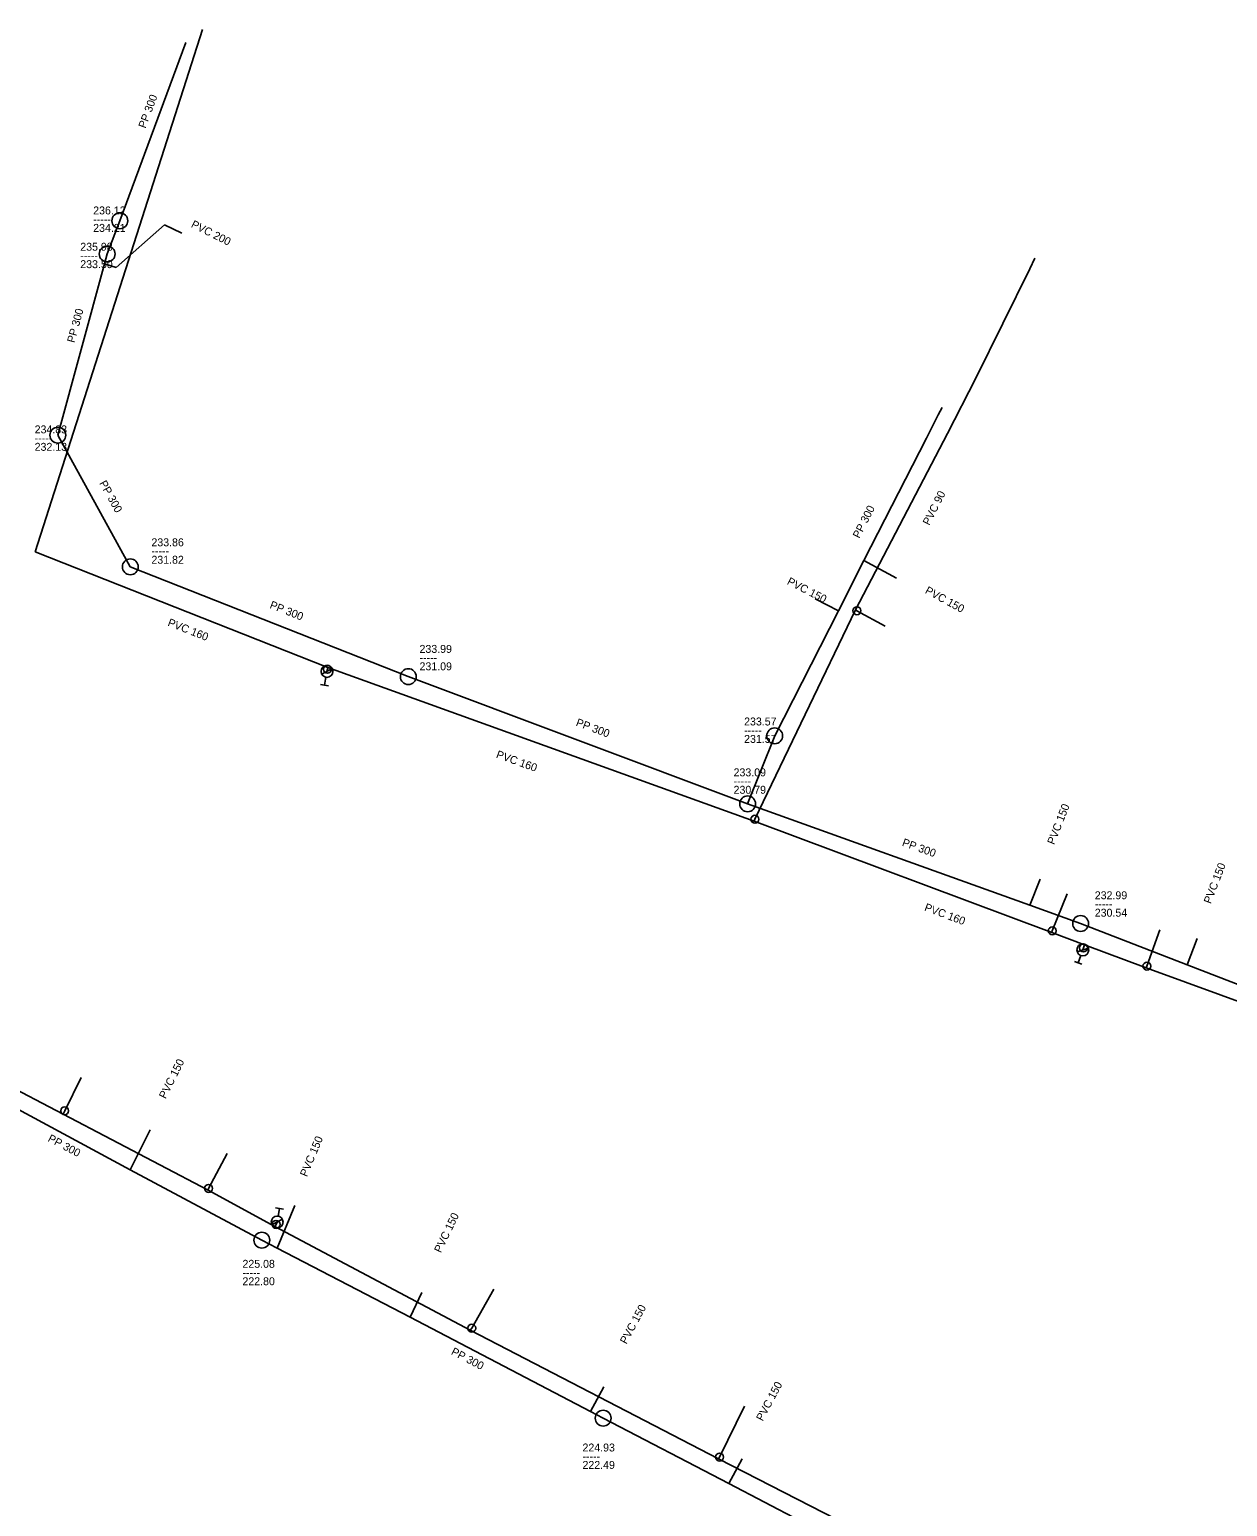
# Model space of a CAD drawing. Extents: x -771542 to -770341, y -1050442 to -1049881.
# Drawn here: x -771242.8 to -771091.6, y -1050160.7 to -1049974.4 of the extents above; entities that cross this region are included whole.
import ezdxf

# ---------------------------------------------------------------- set-up
doc = ezdxf.new("R2010")
doc.units = 0
doc.layers.add('Level 0', color=7, linetype='Continuous')

msp = doc.modelspace()

# ---------------------------------------------------------------- linework, layer by layer
at = {"layer": 'Level 0'}
for p, q in [((-771220.95, -1049974.35), (-771242.06, -1050040.24)), ((-771223.04, -1049976), (-771231.38, -1049998.48)), ((-771231.38, -1049998.48), (-771232.99, -1050002.67)), ((-771231.83, -1050004.36), (-771225.73, -1049999)), ((-771225.73, -1049999), (-771223.55, -1050000.04)), ((-771232.99, -1050002.67), (-771233.33, -1050003.92)), ((-771116.54, -1050004.53), (-771115.9, -1050003.22)), ((-771233.33, -1050003.92), (-771239.22, -1050025.54)), ((-771233.33, -1050003.92), (-771231.83, -1050004.36)), ((-771123.35, -1050018.33), (-771116.54, -1050004.53)), ((-771126.9, -1050025.32), (-771123.35, -1050018.33)), ((-771127.61, -1050022.04), (-771128.08, -1050022.96)), ((-771128.08, -1050022.96), (-771129.59, -1050025.93)), ((-771239.22, -1050025.54), (-771230.07, -1050042.15)), ((-771138.55, -1050047.57), (-771126.9, -1050025.32)), ((-771129.59, -1050025.93), (-771137.46, -1050041.37)), ((-771242.06, -1050040.24), (-771205.12, -1050054.85)), ((-771230.07, -1050042.15), (-771194.98, -1050056.01)), ((-771137.46, -1050041.37), (-771140.68, -1050047.69)), ((-771137.46, -1050041.37), (-771133.36, -1050043.59)), ((-771140.68, -1050047.69), (-771143.62, -1050046.18)), ((-771151.23, -1050074.01), (-771138.55, -1050047.57)), ((-771140.68, -1050047.69), (-771148.73, -1050063.48)), ((-771138.55, -1050047.57), (-771138.35, -1050047.7)), ((-771138.35, -1050047.7), (-771134.78, -1050049.66)), ((-771204.58, -1050055), (-771205.9, -1050055.7)), ((-771205.19, -1050055.08), (-771205.24, -1050055.35)), ((-771205.12, -1050054.85), (-771205.19, -1050055.08)), ((-771205.12, -1050054.85), (-771151.31, -1050074.25)), ((-771205.05, -1050057.16), (-771206.04, -1050056.99)), ((-771205.37, -1050056.09), (-771205.54, -1050057.07)), ((-771194.98, -1050056.01), (-771152.15, -1050072.06)), ((-771148.73, -1050063.48), (-771152.15, -1050072.06)), ((-771152.15, -1050072.06), (-771116.52, -1050084.87)), ((-771151.31, -1050074.25), (-771151.23, -1050074.01)), ((-771151.31, -1050074.25), (-771113.77, -1050088.3)), ((-771116.52, -1050084.87), (-771115.22, -1050081.57)), ((-771113.69, -1050088.09), (-771111.81, -1050083.42)), ((-771116.52, -1050084.87), (-771110.12, -1050087.17)), ((-771110.12, -1050087.17), (-771096.66, -1050092.37)), ((-771113.77, -1050088.3), (-771113.69, -1050088.09)), ((-771113.77, -1050088.3), (-771109.61, -1050089.86)), ((-771101.75, -1050092.55), (-771100.13, -1050087.96)), ((-771096.66, -1050092.37), (-771095.39, -1050089.06)), ((-771109.13, -1050090.26), (-771110.55, -1050090.72)), ((-771110.1, -1050091.19), (-771110.44, -1050092.13)), ((-771109.76, -1050090.25), (-771109.84, -1050090.49)), ((-771109.61, -1050089.86), (-771109.76, -1050090.25)), ((-771109.61, -1050089.86), (-771101.83, -1050092.77)), ((-771109.97, -1050092.31), (-771110.91, -1050091.96)), ((-771101.83, -1050092.77), (-771101.75, -1050092.55)), ((-771101.83, -1050092.77), (-771069.68, -1050104.49)), ((-771096.66, -1050092.37), (-771069.74, -1050102.77)), ((-771252.68, -1050106.1), (-771230.08, -1050118.23)), ((-771238.56, -1050111.22), (-771246.42, -1050107.1)), ((-771238.35, -1050110.8), (-771236.28, -1050106.58)), ((-771238.56, -1050111.22), (-771238.35, -1050110.8)), ((-771220.23, -1050120.83), (-771238.56, -1050111.22)), ((-771230.08, -1050118.23), (-771227.56, -1050113.21)), ((-771220.19, -1050120.59), (-771217.86, -1050116.2)), ((-771230.08, -1050118.23), (-771213.46, -1050127.13)), ((-771220.23, -1050120.83), (-771220.19, -1050120.59)), ((-771211.82, -1050125.38), (-771220.23, -1050120.83)), ((-771211.72, -1050123.03), (-771210.73, -1050123.2)), ((-771211.54, -1050128.13), (-771209.3, -1050122.77)), ((-771212.19, -1050125.19), (-771210.87, -1050124.49)), ((-771211.66, -1050125.14), (-771211.53, -1050124.84)), ((-771211.4, -1050124.1), (-771211.23, -1050123.12)), ((-771211.82, -1050125.38), (-771211.66, -1050125.14)), ((-771211.82, -1050125.38), (-771187.15, -1050138.47)), ((-771213.46, -1050127.13), (-771211.54, -1050128.13)), ((-771211.54, -1050128.13), (-771194.76, -1050136.86)), ((-771194.76, -1050136.86), (-771193.26, -1050133.75)), ((-771186.97, -1050138.23), (-771184.19, -1050133.31)), ((-771194.76, -1050136.86), (-771171.97, -1050148.76)), ((-771187.15, -1050138.47), (-771186.97, -1050138.23)), ((-771187.15, -1050138.47), (-771155.81, -1050154.74)), ((-771171.97, -1050148.76), (-771170.29, -1050145.63)), ((-771171.97, -1050148.76), (-771170.38, -1050149.59)), ((-771155.69, -1050154.5), (-771152.54, -1050148.08)), ((-771170.38, -1050149.59), (-771154.52, -1050157.84)), ((-771155.81, -1050154.74), (-771155.69, -1050154.5)), ((-771154.52, -1050157.84), (-771152.84, -1050154.7)), ((-771155.81, -1050154.74), (-771094.72, -1050185.98)), ((-771154.52, -1050157.84), (-771125.58, -1050172.94))]:
    msp.add_line(p, q, dxfattribs=at)
for centre, radius in [((-771231.38, -1049998.48), 1), ((-771232.99, -1050002.67), 1), ((-771239.22, -1050025.54), 1), ((-771230.07, -1050042.15), 1), ((-771138.35, -1050047.7), 0.5), ((-771205.24, -1050055.35), 0.75), ((-771205.19, -1050055.08), 0.5), ((-771194.98, -1050056.01), 1), ((-771148.73, -1050063.48), 1), ((-771152.15, -1050072.06), 1), ((-771151.23, -1050074.01), 0.5), ((-771113.69, -1050088.09), 0.5), ((-771110.12, -1050087.17), 1), ((-771109.84, -1050090.49), 0.75), ((-771109.76, -1050090.25), 0.5), ((-771101.75, -1050092.55), 0.5), ((-771238.35, -1050110.8), 0.5), ((-771220.19, -1050120.59), 0.5), ((-771211.53, -1050124.84), 0.75), ((-771211.66, -1050125.14), 0.5), ((-771213.46, -1050127.13), 1), ((-771186.97, -1050138.23), 0.5), ((-771170.38, -1050149.59), 1), ((-771155.69, -1050154.5), 0.5)]:
    msp.add_circle(centre, radius, dxfattribs=at)

# ---------------------------------------------------------------- texts
for s, rotation, p in [('PP 300', 69.645, (-771228.15, -1049986.89)), ('PVC 200', 333.325, (-771222.48, -1049999.25)), ('PP 300', 74.784, (-771237.11, -1050013.95)), ('PP 300', 298.849, (-771234.01, -1050031.59)), ('PVC 90', 63.075, (-771129.22, -1050037)), ('PP 300', 62.991, (-771138.05, -1050038.64)), ('PVC 150', 332.815, (-771147.26, -1050044.31)), ('PVC 150', 331.566, (-771129.84, -1050045.44)), ('PP 300', 338.447, (-771212.55, -1050047.34)), ('PVC 160', 338.421, (-771225.43, -1050049.56)), ('PP 300', 339.457, (-771173.9, -1050062.18)), ('PVC 160', 340.174, (-771183.97, -1050066.22)), ('PVC 150', 68.499, (-771113.45, -1050077.29)), ('PP 300', 340.225, (-771132.73, -1050077.33)), ('PVC 150', 69.009, (-771093.69, -1050084.75)), ('PVC 160', 339.444, (-771129.92, -1050085.51)), ('PVC 150', 63.344, (-771225.61, -1050109.36)), ('PP 300', 331.776, (-771240.56, -1050114.59)), ('PVC 150', 67.319, (-771207.78, -1050119.2)), ('PVC 150', 64.251, (-771190.87, -1050128.8)), ('PVC 150', 61.776, (-771167.45, -1050140.32)), ('PP 300', 332.428, (-771189.66, -1050141.5)), ('PVC 150', 61.852, (-771150.25, -1050150.04))]:
    msp.add_text(s, height=1, rotation=rotation, dxfattribs=at).set_placement(p)
for s, p in [('236.12', (-771234.75, -1049997.68)), ('-----', (-771234.75, -1049998.78)), ('234.21', (-771234.75, -1049999.88)), ('235.98', (-771236.38, -1050002.26)), ('-----', (-771236.38, -1050003.36)), ('233.50', (-771236.38, -1050004.46)), ('-----', (-771242.14, -1050026.41)), ('234.83', (-771242.14, -1050025.31)), ('232.13', (-771242.14, -1050027.51)), ('233.86', (-771227.4, -1050039.56)), ('-----', (-771227.4, -1050040.66)), ('231.82', (-771227.4, -1050041.76)), ('233.99', (-771193.56, -1050053.01)), ('-----', (-771193.56, -1050054.11)), ('231.09', (-771193.56, -1050055.21)), ('233.57', (-771152.59, -1050062.17)), ('-----', (-771152.59, -1050063.27)), ('231.57', (-771152.59, -1050064.37)), ('233.09', (-771153.92, -1050068.59)), ('-----', (-771153.92, -1050069.69)), ('230.79', (-771153.92, -1050070.79)), ('232.99', (-771108.33, -1050084.1)), ('-----', (-771108.33, -1050085.2)), ('230.54', (-771108.33, -1050086.3)), ('225.08', (-771215.91, -1050130.61)), ('-----', (-771215.91, -1050131.71)), ('222.80', (-771215.91, -1050132.81)), ('224.93', (-771172.99, -1050153.79)), ('-----', (-771172.99, -1050154.89)), ('222.49', (-771172.99, -1050155.99))]:
    msp.add_text(s, height=1, dxfattribs=at).set_placement(p)

doc.saveas('drawing.dxf')
